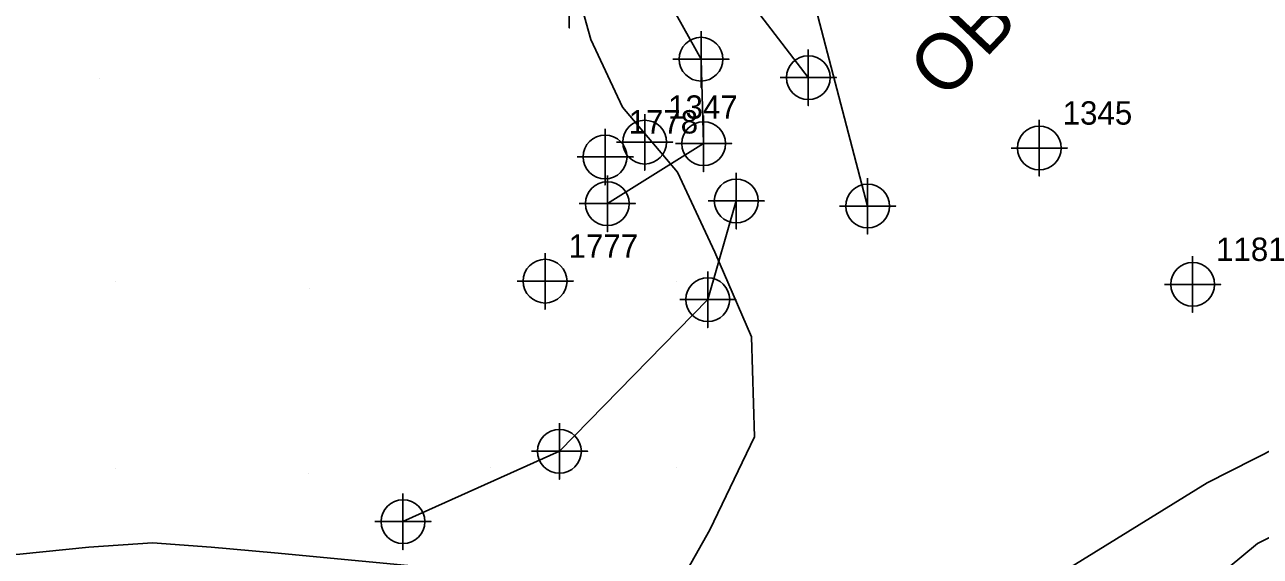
# Model space of a CAD drawing. Extents: x 1497074 to 1501343, y 481943 to 486114.
# Drawn here: x 1498718.1 to 1498850.2, y 484795.7 to 484852.6 of the extents above; entities that cross this region are included whole.
import ezdxf

# ---------------------------------------------------------------- set-up
doc = ezdxf.new("R2010")
doc.units = 0
for name, color, linetype in [('Exist DTM Breakline', 7, 'Continuous'), ('Exist DTM Breakline Cogo Point CELL', 7, 'Continuous'), ('Exist DTM Regular Point CELL', 7, 'Continuous'), ('Exist DTM Regular Point Cogo Number', 7, 'Continuous'), ('PH Exist DTM Breakline', 7, 'Continuous'), ('PH Exist DTM Obscure Area', 7, 'Continuous'), ('PH Exist DTM Obscure Area Text', 7, 'Continuous'), ('PH Exist DTM Point', 7, 'Continuous')]:
    doc.layers.add(name, color=color, linetype=linetype)

msp = doc.modelspace()

# ---------------------------------------------------------------- linework, layer by layer
at = {"layer": 'Exist DTM Breakline'}
for points in [[(1498808.2, 484833.18), (1498802.07, 484856.65), (1498795.16, 484873.78), (1498778.55, 484891.85), (1498758.28, 484902.66), (1498731.74, 484910.66), (1498709.09, 484916.99)], [(1498703.32, 484894.97), (1498713.52, 484880.84), (1498750.48, 484874.03), (1498781.67, 484873.31), (1498801.86, 484846.92)], [(1498780.39, 484833.44), (1498790.68, 484839.86), (1498790.4, 484848.89), (1498781.12, 484865.58), (1498774.37, 484867.84), (1498762.02, 484859.08)], [(1498794.16, 484833.73), (1498791.12, 484823.18), (1498775.27, 484806.96), (1498758.55, 484799.43)]]:
    msp.add_lwpolyline(points, dxfattribs=at)
at = {"layer": 'Exist DTM Breakline Cogo Point CELL'}
for points in [[(1498790.4, 484851.89), (1498790.4, 484845.89), (1498790.4, 484848.89), (1498793.4, 484848.89), (1498787.4, 484848.89)], [(1498801.86, 484849.92), (1498801.86, 484843.92), (1498801.86, 484846.92), (1498804.86, 484846.92), (1498798.86, 484846.92)], [(1498790.68, 484842.86), (1498790.68, 484836.86), (1498790.68, 484839.86), (1498793.68, 484839.86), (1498787.68, 484839.86)], [(1498780.39, 484836.44), (1498780.39, 484830.44), (1498780.39, 484833.44), (1498783.39, 484833.44), (1498777.39, 484833.44)], [(1498794.16, 484836.73), (1498794.16, 484830.73), (1498794.16, 484833.73), (1498797.16, 484833.73), (1498791.16, 484833.73)], [(1498808.2, 484836.18), (1498808.2, 484830.18), (1498808.2, 484833.18), (1498811.2, 484833.18), (1498805.2, 484833.18)], [(1498791.12, 484826.18), (1498791.12, 484820.18), (1498791.12, 484823.18), (1498794.12, 484823.18), (1498788.12, 484823.18)], [(1498775.27, 484809.96), (1498775.27, 484803.96), (1498775.27, 484806.96), (1498778.27, 484806.96), (1498772.27, 484806.96)], [(1498758.55, 484802.43), (1498758.55, 484796.43), (1498758.55, 484799.43), (1498761.55, 484799.43), (1498755.55, 484799.43)]]:
    msp.add_lwpolyline(points, dxfattribs=at)
for centre in [(1498790.4, 484848.89), (1498801.86, 484846.92), (1498790.68, 484839.86), (1498794.16, 484833.73), (1498780.39, 484833.44), (1498808.2, 484833.18), (1498791.12, 484823.18), (1498775.27, 484806.96), (1498758.55, 484799.43)]:
    msp.add_circle(centre, 2.34, dxfattribs=at)
at = {"layer": 'Exist DTM Regular Point CELL'}
for points in [[(1498776.31, 484858.24), (1498776.31, 484852.24), (1498776.31, 484855.24), (1498779.31, 484855.24), (1498773.31, 484855.24)], [(1498784.38, 484843.02), (1498784.38, 484837.02), (1498784.38, 484840.02), (1498787.38, 484840.02), (1498781.38, 484840.02)], [(1498780.15, 484841.44), (1498780.15, 484835.44), (1498780.15, 484838.44), (1498783.15, 484838.44), (1498777.15, 484838.44)], [(1498826.54, 484842.39), (1498826.54, 484836.39), (1498826.54, 484839.39), (1498829.54, 484839.39), (1498823.54, 484839.39)], [(1498773.74, 484828.15), (1498773.74, 484822.15), (1498773.74, 484825.15), (1498776.74, 484825.15), (1498770.74, 484825.15)], [(1498842.93, 484827.81), (1498842.93, 484821.81), (1498842.93, 484824.81), (1498845.93, 484824.81), (1498839.93, 484824.81)]]:
    msp.add_lwpolyline(points, dxfattribs=at)
for centre in [(1498784.38, 484840.02), (1498826.54, 484839.39), (1498780.15, 484838.44), (1498773.74, 484825.15), (1498842.93, 484824.81)]:
    msp.add_circle(centre, 2.34, dxfattribs=at)
at = {"layer": 'PH Exist DTM Breakline'}
for points in [[(1498871.75, 484817.91), (1498862.06, 484812.48), (1498844.48, 484803.59), (1498816.16, 484786.08)], [(1498751.28, 484759.9), (1498758.99, 484762.13), (1498767.46, 484763.96), (1498776.63, 484766.15), (1498786.71, 484768.77), (1498797.68, 484771.65), (1498806.73, 484773.91), (1498815.79, 484776.07), (1498824.19, 484778.19), (1498831.77, 484781.06), (1498838.18, 484786.15), (1498843.82, 484792.08), (1498849.87, 484797.11), (1498857.7, 484800.99), (1498865.48, 484804.27), (1498872, 484807.32), (1498879.68, 484809.61), (1498887.65, 484811.86), (1498895.42, 484813.08), (1498901.06, 484810.76), (1498906.62, 484808.24), (1498910.07, 484805.42)], [(1498763.56, 484794.31), (1498744.83, 484796.11), (1498738.07, 484796.71), (1498731.78, 484797.17), (1498724.97, 484796.7), (1498717.62, 484795.94), (1498710.92, 484795.54), (1498704.32, 484795.61), (1498698.28, 484794.78), (1498694.33, 484791.72), (1498692.02, 484789.28), (1498685.41, 484785.03), (1498678.23, 484782.05), (1498671.57, 484779.37), (1498664.71, 484774.06), (1498660.11, 484769.43), (1498655.29, 484764.35), (1498651.54, 484760.4), (1498646.8, 484755.42), (1498641.81, 484751.48), (1498635.97, 484749.35), (1498631.53, 484748.05)]]:
    msp.add_lwpolyline(points, dxfattribs=at)
at = {"layer": 'PH Exist DTM Obscure Area'}
msp.add_lwpolyline([(1498786.33, 484789.65), (1498791.34, 484798.56), (1498796.13, 484808.5), (1498795.79, 484819.2), (1498791.87, 484828.24), (1498787.89, 484836.82), (1498782, 484843.75), (1498778.61, 484850.99), (1498776.52, 484858.55)], dxfattribs=at)
at = {"layer": 'PH Exist DTM Point'}
for p, q in [((1498726.1, 484846.78), (1498726.1, 484846.78)), ((1498727.81, 484825.16), (1498727.81, 484825.16)), ((1498748.6, 484824.41), (1498748.6, 484824.41)), ((1498787.81, 484825.16), (1498787.81, 484825.16)), ((1498727.81, 484805.16), (1498727.81, 484805.16)), ((1498748.47, 484804.54), (1498748.47, 484804.54)), ((1498767.87, 484805.22), (1498767.87, 484805.22)), ((1498787.74, 484805.23), (1498787.74, 484805.23))]:
    msp.add_line(p, q, dxfattribs=at)

# ---------------------------------------------------------------- texts
at = {"layer": 'Exist DTM Regular Point Cogo Number'}
for s, p in [('1347', (1498786.88, 484842.52)), ('1345', (1498829.04, 484841.89)), ('1778', (1498782.65, 484840.94)), ('1777', (1498776.24, 484827.65)), ('1181', (1498845.43, 484827.31))]:
    msp.add_text(s, height=2.5, dxfattribs=at).set_placement(p)
at = {"layer": 'PH Exist DTM Obscure Area Text'}
msp.add_text('OBSCURED', height=6, rotation=46.4845, dxfattribs=at).set_placement((1498816.47, 484844.37))

doc.saveas('drawing.dxf')
